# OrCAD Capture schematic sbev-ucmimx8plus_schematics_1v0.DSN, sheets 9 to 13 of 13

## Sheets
9 09. Audio Codec: size A3; title: SBEV-UCMIMX8PLUS      09. AUDIO CODEC
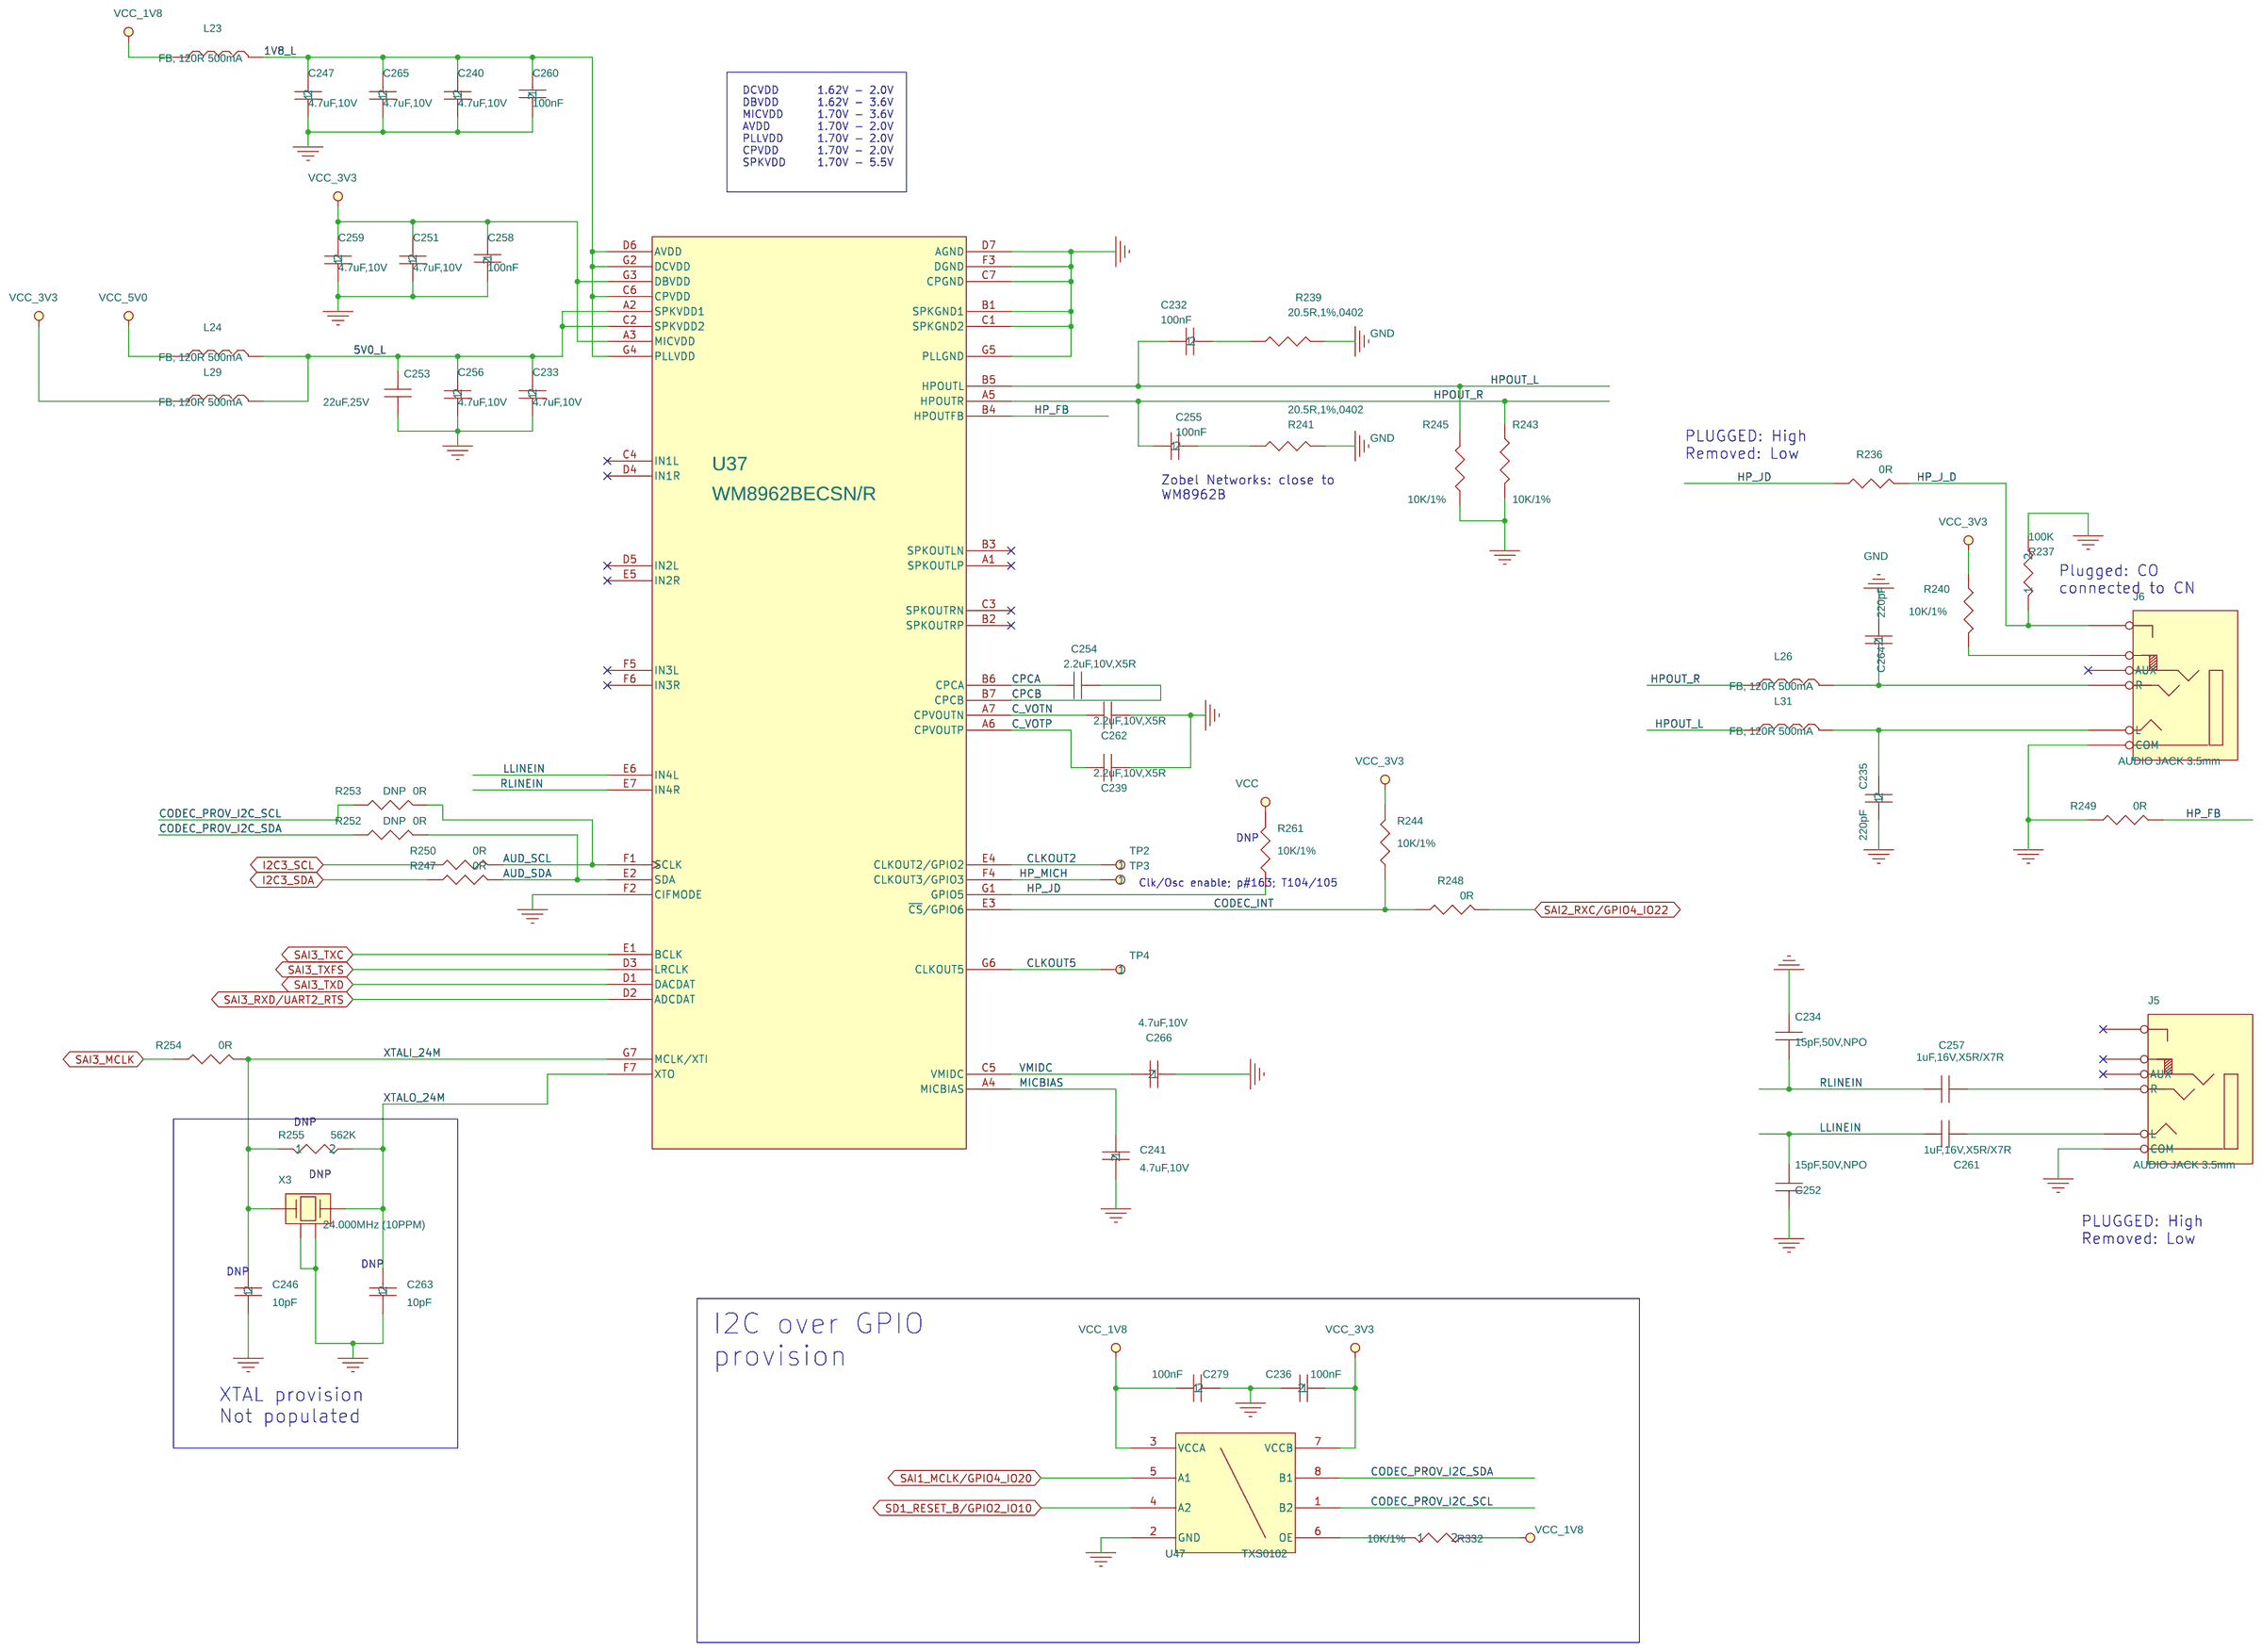
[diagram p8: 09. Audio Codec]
10 06. USB #2 and mini-PCIe: size A3; title: SBEV-UCMIMX8PLUS   06. USB #2 and mini-PCIe
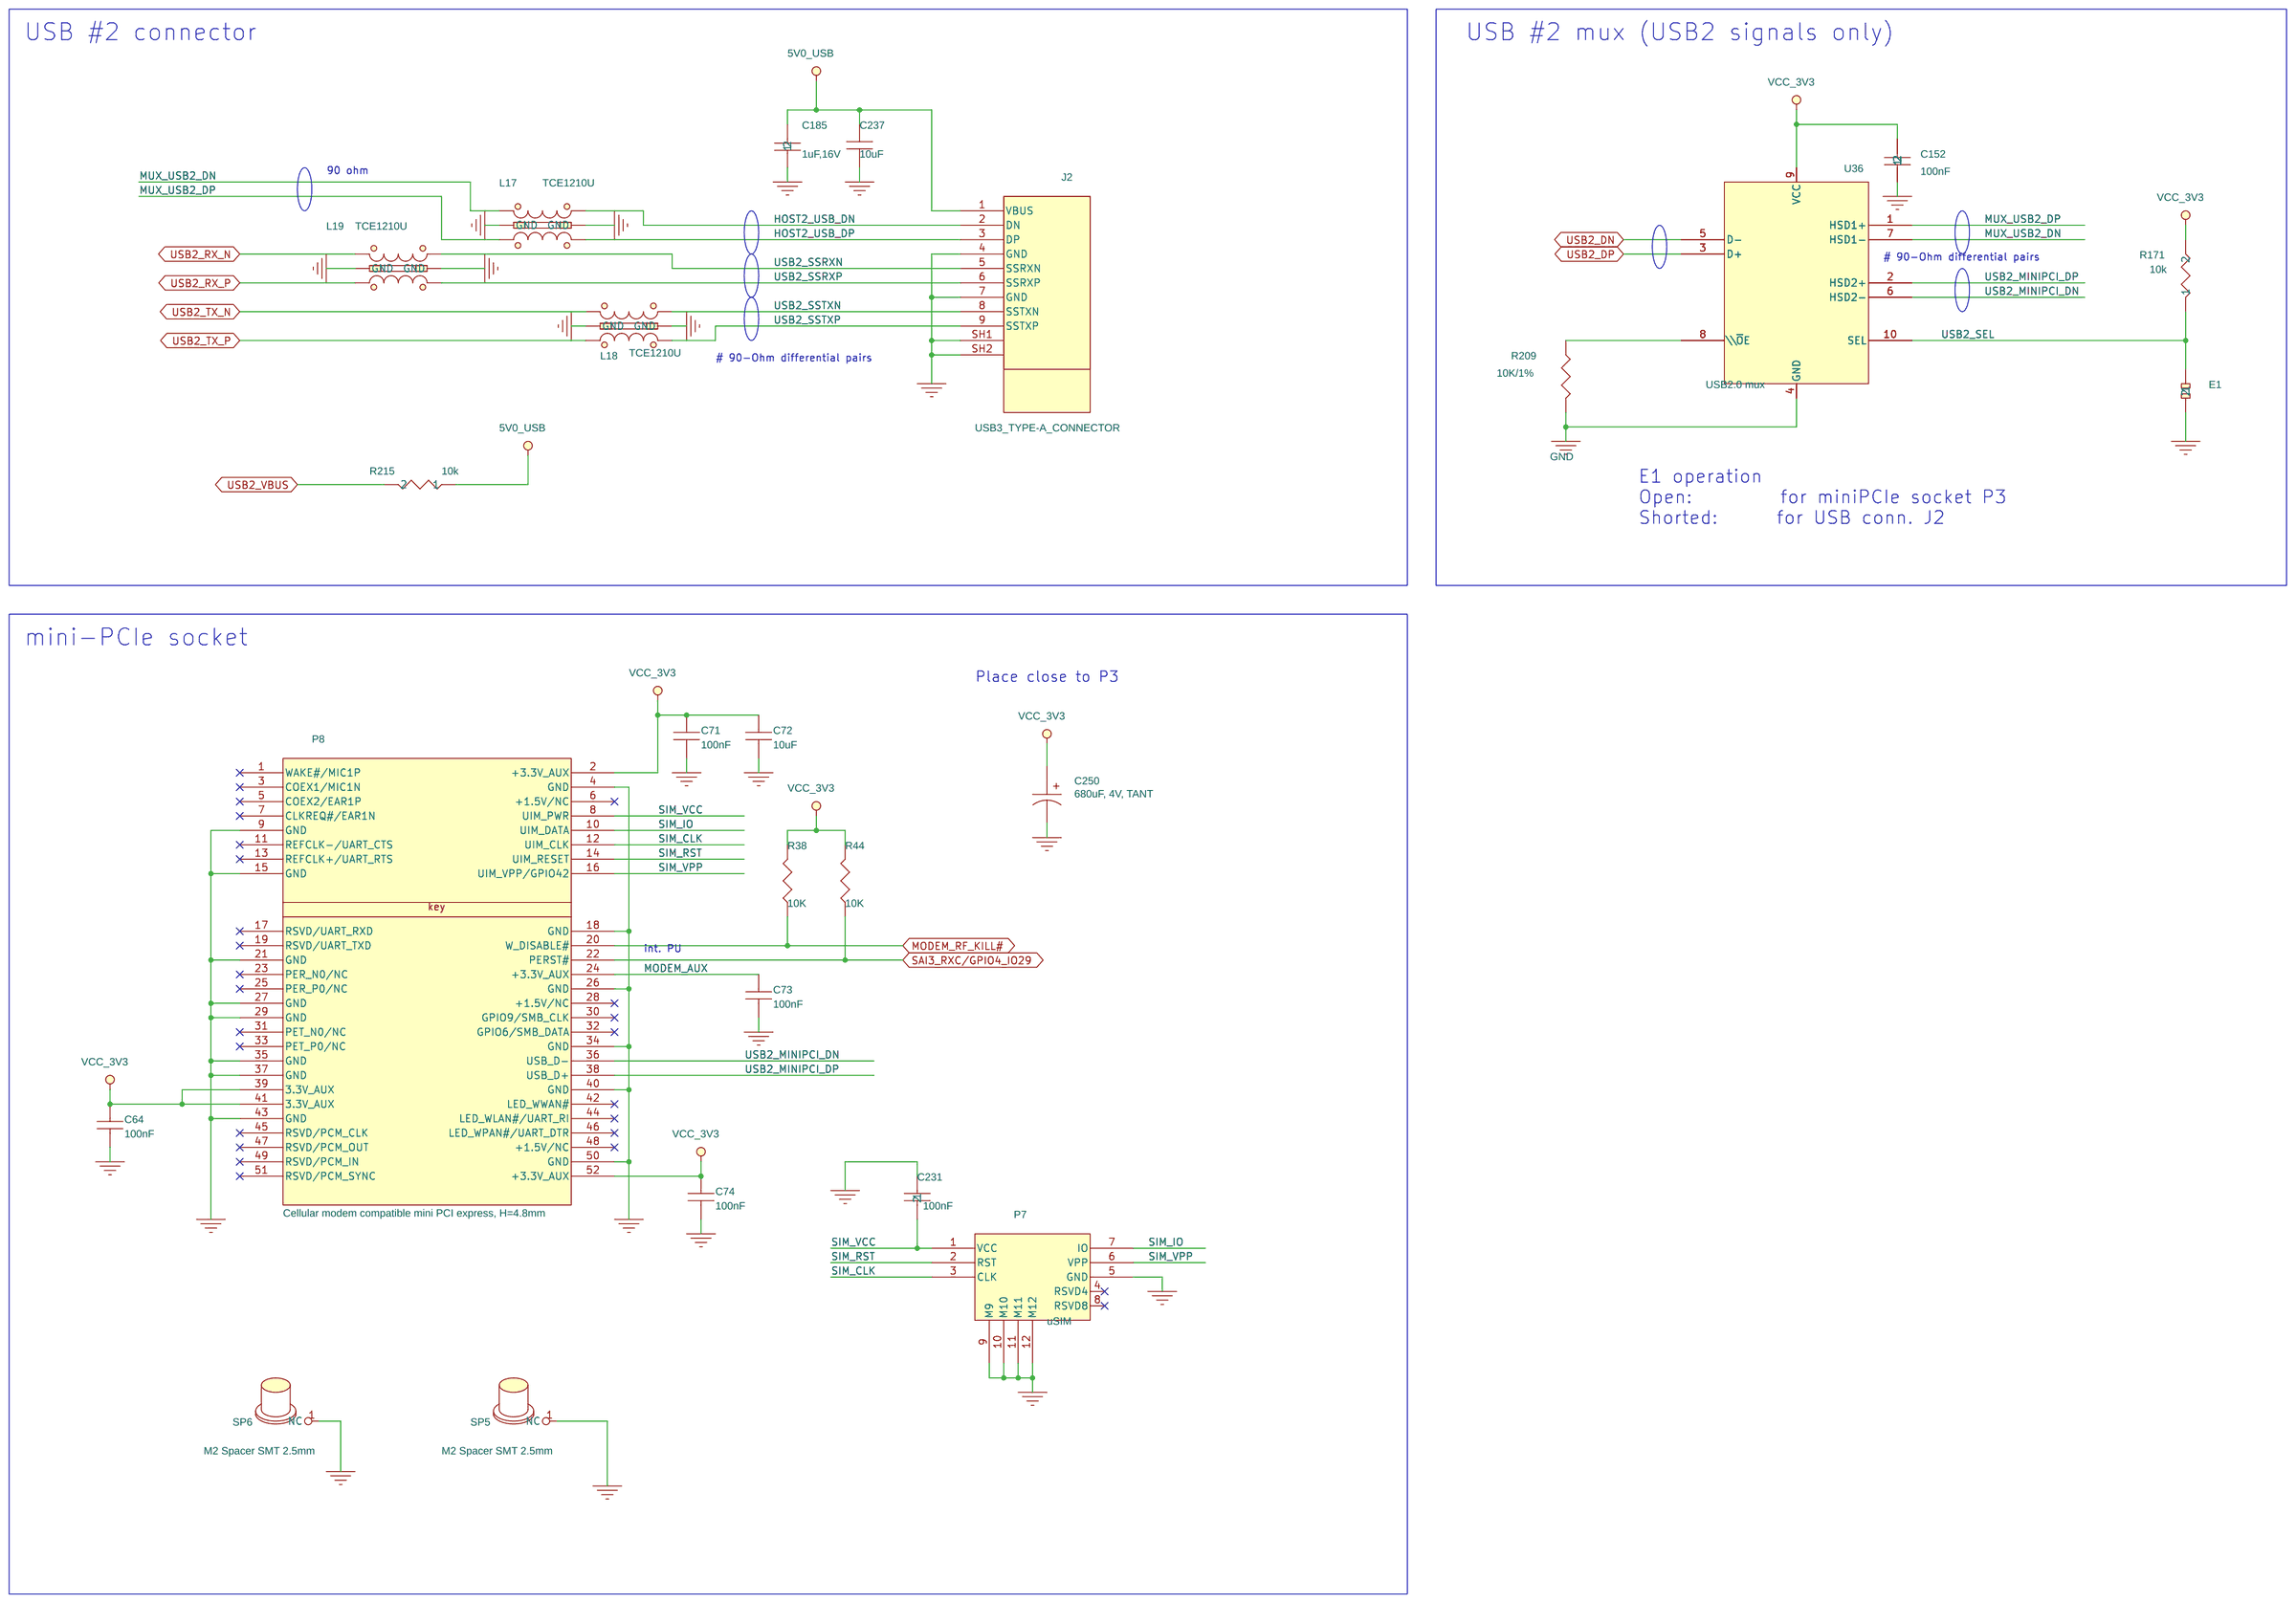
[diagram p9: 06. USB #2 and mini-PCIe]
11 13. DC input and spacers: size A3; title: SBEV-UCMIMX8PLUS    13. POWER
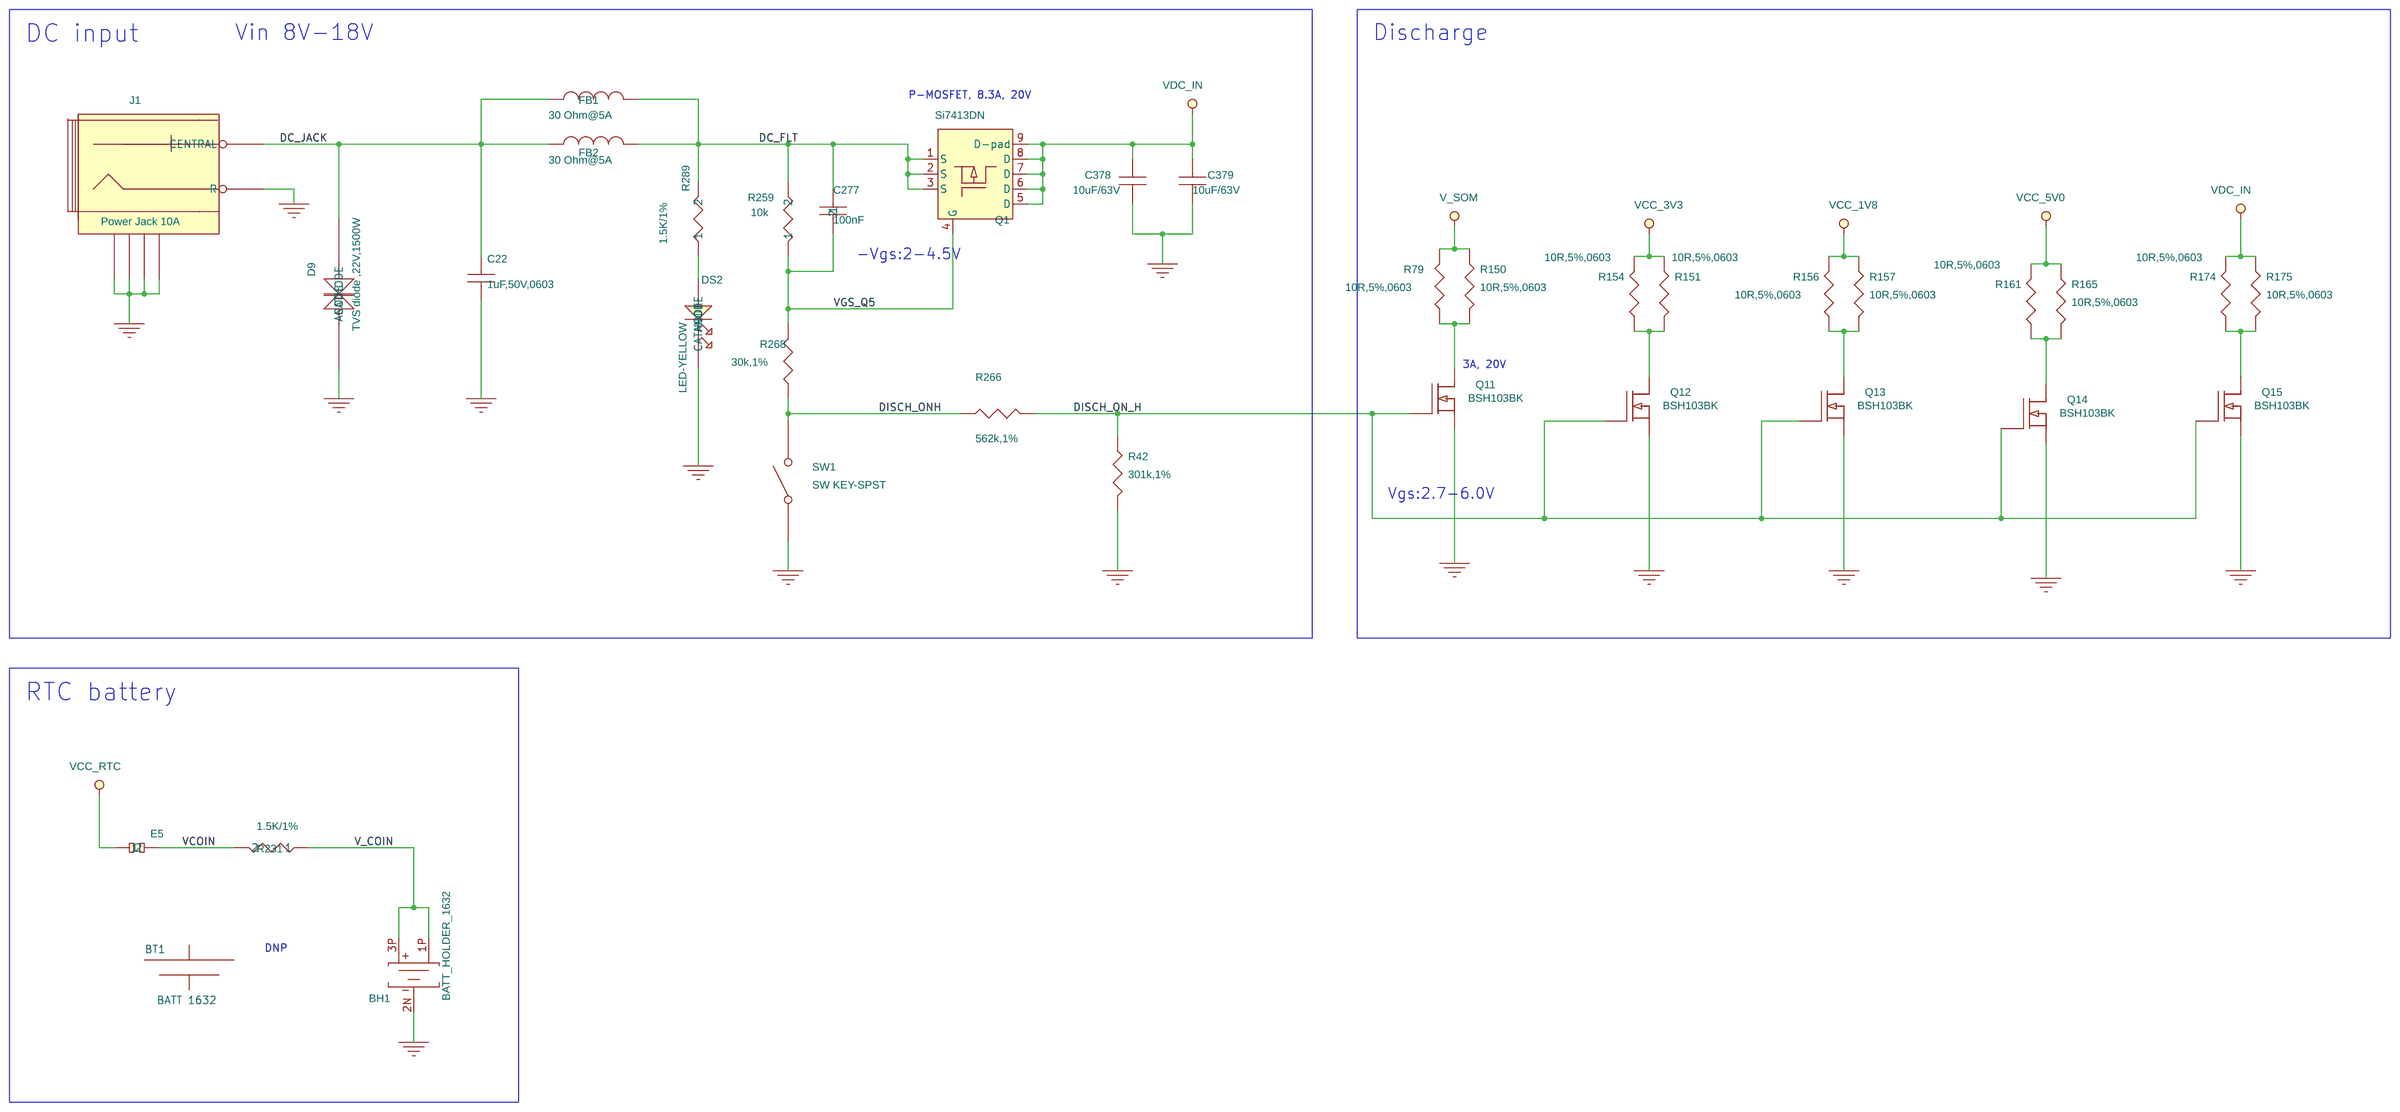
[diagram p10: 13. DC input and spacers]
12 12. Power: size A3; title: SBEV-UCMIMX8PLUS      12. Power
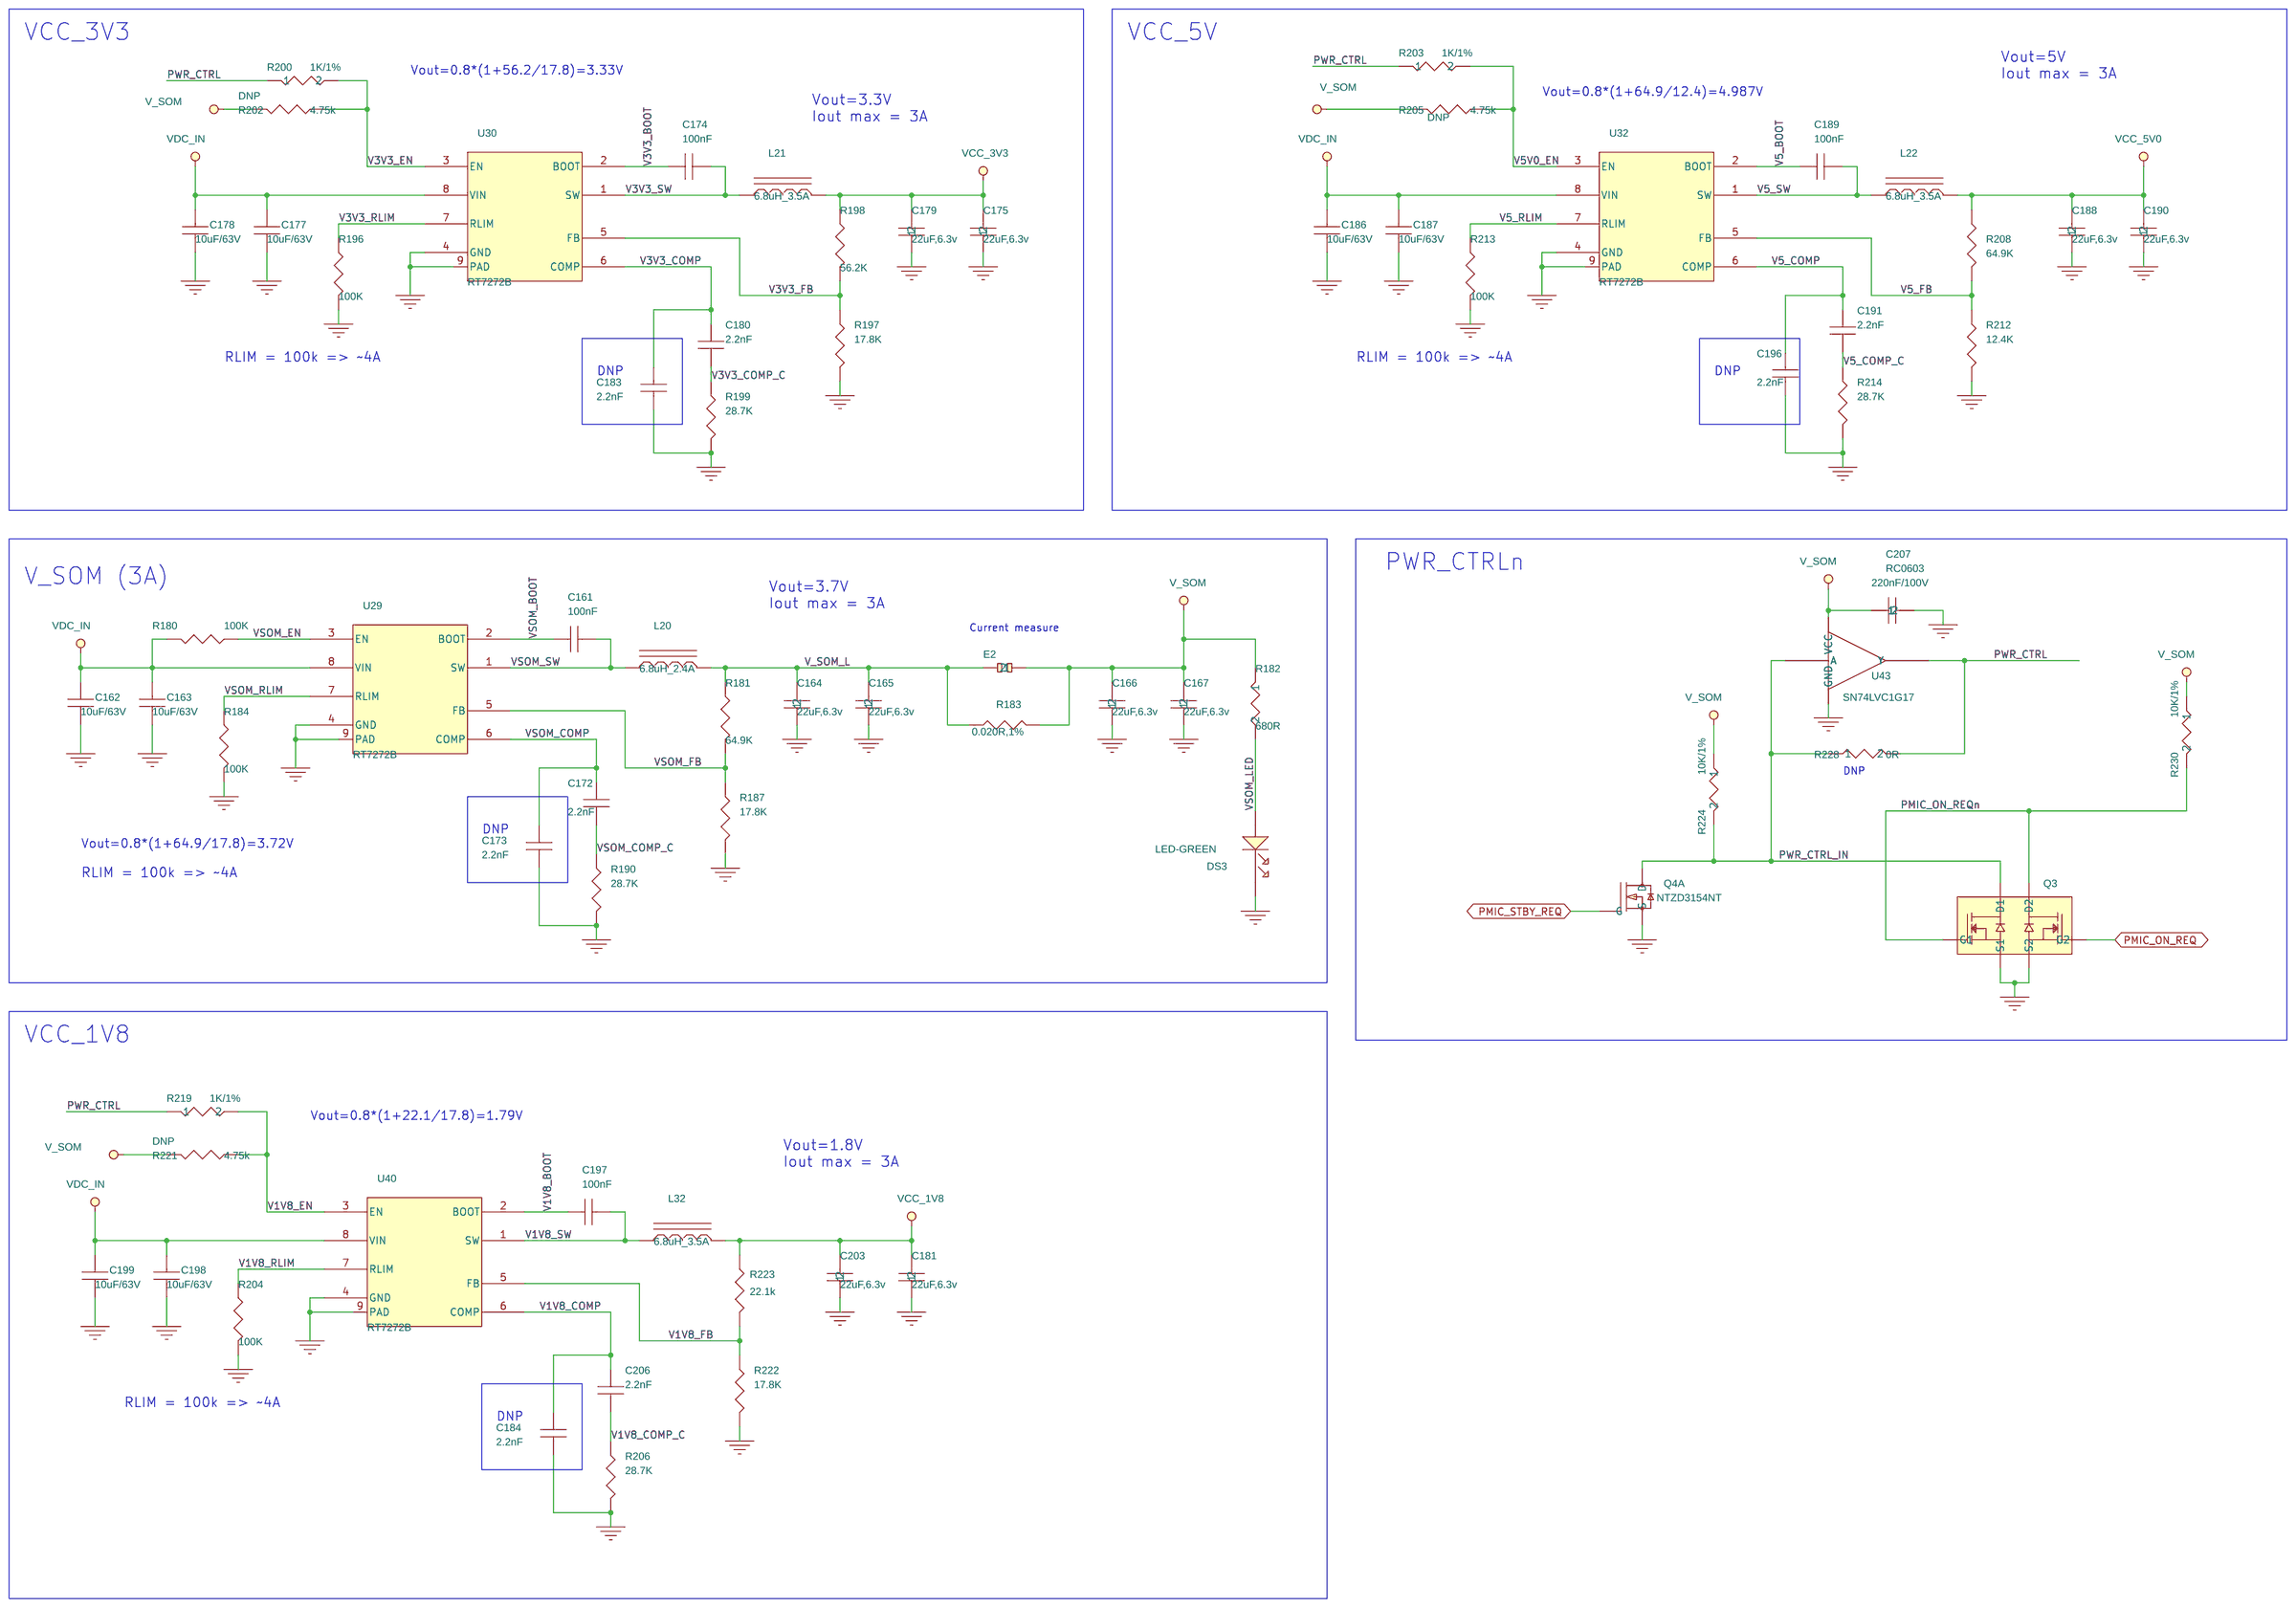
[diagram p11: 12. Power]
13 10. I/O headers, JTAG, GPIO exp: size A3; title: SBEV-UCMIMX8PLUS      10. UART, CAN, SPI, I2C, MISC
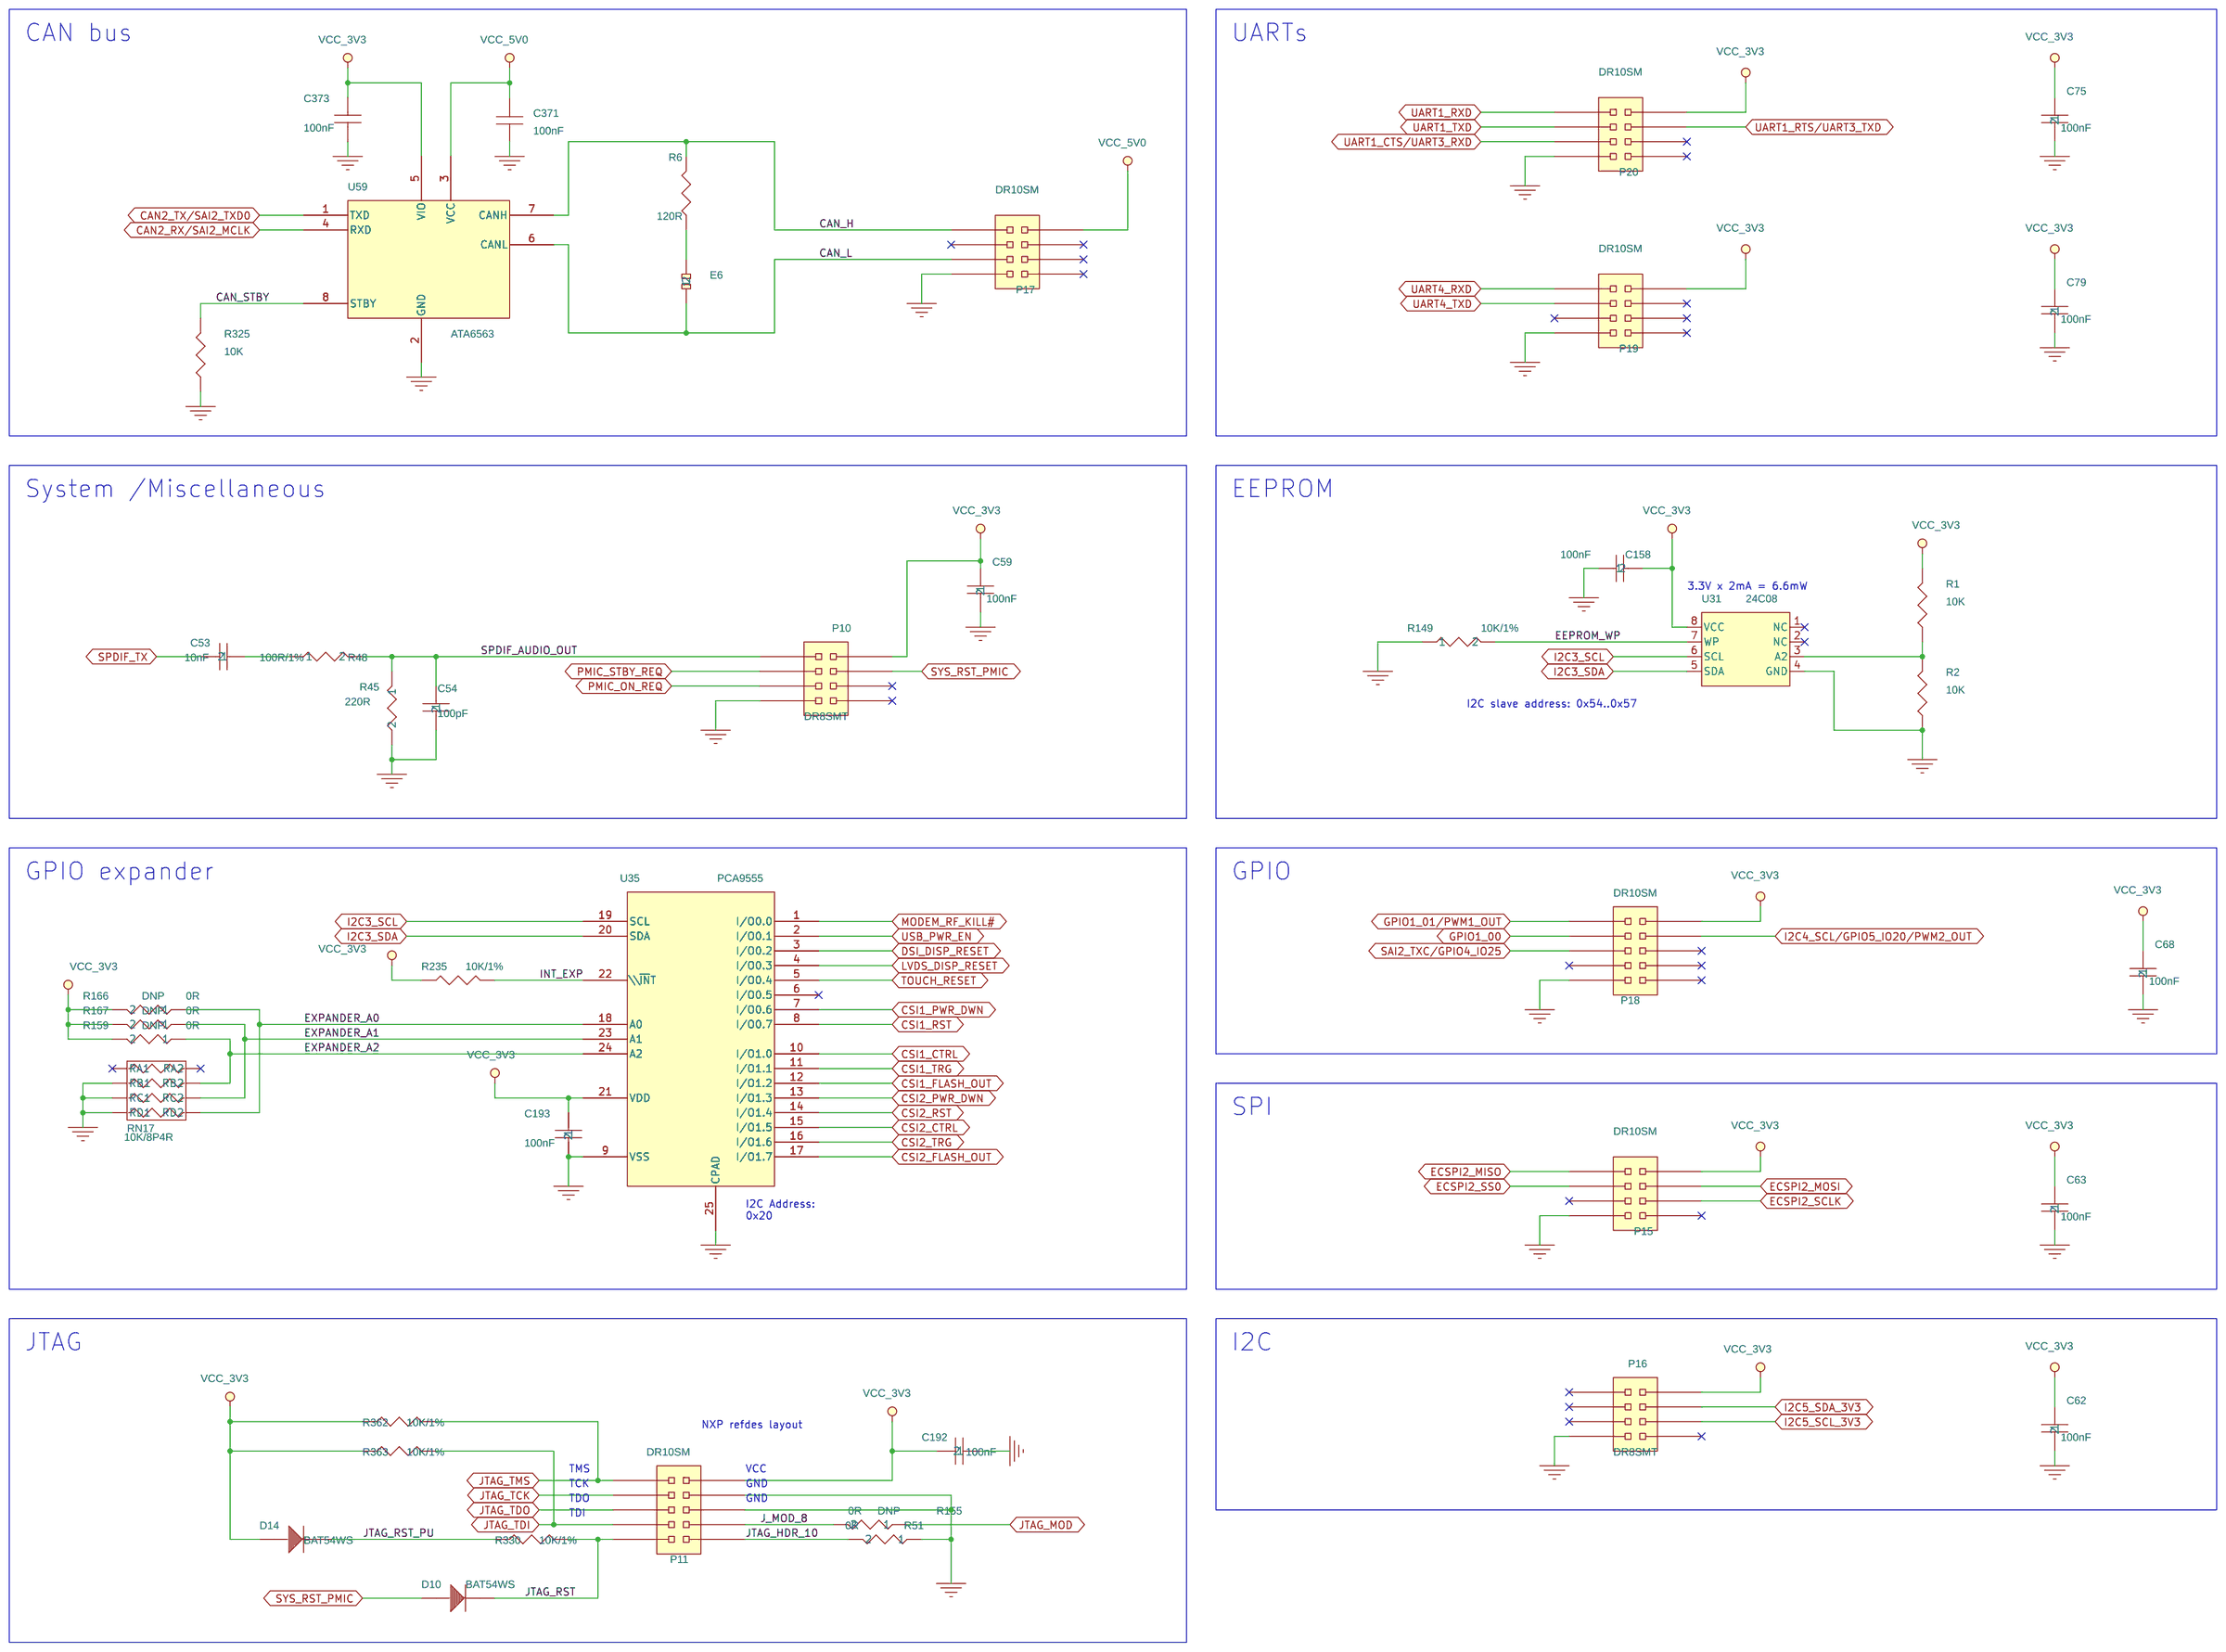
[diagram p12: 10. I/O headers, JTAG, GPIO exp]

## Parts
sheet 06. USB #2 and mini-PCIe
C64  100nF  [RC0402]
C71  100nF  [RC0402]
C72  10uF  [RC0603]
C73  100nF  [RC0402]
C74  100nF  [RC0402]
C152  100nF  [RC0402]
C185  1uF,16V  [RC0402]
C231  100nF  [RC0402]
C237  10uF  [C0603-08]
C250  680uF, 4V, TANT  [TANT7343]
E1  HDR1X2  [1X2THHDR]
J2  USB3_TYPE-A_CONNECTOR  [USB3_TYPEA]
L17  TCE1210U  [EMI1012-ESD]
L18  TCE1210U  [EMI1012-ESD]
L19  TCE1210U  [EMI1012-ESD]
P7  uSIM  [SKT-MicroSIM6-SM]
P8  Cellular modem compatible mini PCI express, H=4.8mm  [MINIPCIE-4]
R38  10K  [RC0402]
R44  10K  [RC0402]
R171  10k  [RC0402]
R209  10K/1%  [RC0402]
R215  10k  [RC0402]
SP5  M2 Spacer SMT 2.5mm  [SpacerM2H4SM]
SP6  M2 Spacer SMT 2.5mm  [SpacerM2H4SM]
U36  USB2.0 mux  [MO-255U1418E]
sheet 09. Audio Codec
C232  100nF  [RC0402]
C233  4.7uF,10V  [RC0402]
C234  15pF,50V,NPO  [RC0402]
C235  220pF  [RC0603]
C236  100nF  [RC0402]
C239  2.2uF,10V,X5R  [RC0402]
C240  4.7uF,10V  [RC0402]
C241  4.7uF,10V  [RC0402]
C246  10pF  [RC0402]
C247  4.7uF,10V  [RC0402]
C251  4.7uF,10V  [RC0402]
C252  15pF,50V,NPO  [RC0402]
C253  22uF,25V  [C0805]
C254  2.2uF,10V,X5R  [RC0402]
C255  100nF  [RC0402]
C256  4.7uF,10V  [RC0402]
C257  1uF,16V,X5R/X7R  [RC0402]
C258  100nF  [RC0402]
C259  4.7uF,10V  [RC0402]
C260  100nF  [RC0402]
C261  1uF,16V,X5R/X7R  [RC0402]
C262  2.2uF,10V,X5R  [RC0402]
C263  10pF  [RC0402]
C264  220pF  [RC0603]
C265  4.7uF,10V  [RC0402]
C266  4.7uF,10V  [RC0402]
C279  100nF  [RC0402]
J5  AUDIO JACK 3.5mm  [AJ35-4P-SW-SM]
J6  AUDIO JACK 3.5mm  [AJ35-4P-SW-SM]
L23  FB, 120R 500mA  [FB0402]
L24  FB, 120R 500mA  [FB0402]
L26  FB, 120R 500mA  [FB0402]
L29  FB, 120R 500mA  [FB0402]
L31  FB, 120R 500mA  [FB0402]
R236  0R  [RC0402]
R237  100K  [RC0402]
R239  20.5R,1%,0402  [RC0402]
R240  10K/1%  [RC0402]
R241  20.5R,1%,0402  [RC0402]
R243  10K/1%  [RC0402]
R244  10K/1%  [RC0402]
R245  10K/1%  [RC0402]
R247  0R  [RC0402]
R248  0R  [RC0402]
R249  0R  [RC0402]
R250  0R  [RC0402]
R252  0R  [RC0402]
R253  0R  [RC0402]
R254  0R  [RC0402]
R255  562K  [RC0402]
R261  10K/1%  [RC0402]
R332  10K/1%  [RC0402]
TP2  TESTPOINT SMT  [TESTPOINT]
TP3  TESTPOINT SMT  [TESTPOINT]
TP4  TESTPOINT SMT  [TESTPOINT]
U37  WM8962BECSN/R  [BGA49_0P5_3P62X4]
U47  TXS0102  [MO-187DA-8]
X3  24.000MHz (10PPM)  [OSC3225]
sheet 10. I/O headers, JTAG, GPIO exp
C53  10nF  [RC0402]
C54  100pF  [RC0402]
C59  100nF  [RC0402]
C62  100nF  [RC0402]
C63  100nF  [RC0402]
C68  100nF  [RC0402]
C75  100nF  [RC0402]
C79  100nF  [RC0402]
C158  100nF  [RC0402]
C192  100nF  [RC0402]
C193  100nF  [RC0402]
C371  100nF  [RC0402]
C373  100nF  [RC0402]
D10  BAT54WS  [SOD-323]
D14  BAT54WS  [SOD-323]
E6  HDR1X2  [1X2THHDR]
P10  DR8SMT  [2X4SMHDR]
P11  DR10SM  [2X5SMHDR]
P15  DR10SM  [2X4SMHDR]
P16  DR8SMT  [2X4SMHDR]
P17  DR10SM  [2X4SMHDR]
P18  DR10SM  [2X5SMHDR]
P19  DR10SM  [2X4SMHDR]
P20  DR10SM  [2X4SMHDR]
R1  10K  [RC0402]
R2  10K  [RC0402]
R6  120R  [RC0402]
R45  220R  [RC0402]
R48  100R/1%  [RC0402]
R51  0R  [RC0402]
R149  10K/1%  [RC0402]
R155  0R  [RC0402]
R159  0R  [RC0402]
R166  0R  [RC0402]
R167  0R  [RC0402]
R235  10K/1%  [RC0402]
R325  10K  [RC0402]
R330  10K/1%  [RC0402]
R362  10K/1%  [RC0402]
R363  10K/1%  [RC0402]
RN17  10K/8P4R  [RESNET8P0805]
U31  24C08  [MO-229VCED-2]
U35  PCA9555  [QFN4x4-24]
U59  ATA6563  [SOI8-150]
sheet 12. Power
C161  100nF  [RC0402]
C162  10uF/63V  [C1210H2_5]
C163  10uF/63V  [C1210H2_5]
C164  22uF,6.3v  [RC0603]
C165  22uF,6.3v  [RC0603]
C166  22uF,6.3v  [RC0603]
C167  22uF,6.3v  [RC0603]
C172  2.2nF  [RC0402]
C173  2.2nF  [RC0402]
C174  100nF  [RC0402]
C175  22uF,6.3v  [RC0603]
C177  10uF/63V  [C1210H2_5]
C178  10uF/63V  [C1210H2_5]
C179  22uF,6.3v  [RC0603]
C180  2.2nF  [RC0402]
C181  22uF,6.3v  [RC0603]
C183  2.2nF  [RC0402]
C184  2.2nF  [RC0402]
C186  10uF/63V  [C1210H2_5]
C187  10uF/63V  [C1210H2_5]
C188  22uF,6.3v  [RC0603]
C189  100nF  [RC0402]
C190  22uF,6.3v  [RC0603]
C191  2.2nF  [RC0402]
C196  2.2nF  [RC0402]
C197  100nF  [RC0402]
C198  10uF/63V  [C1210H2_5]
C199  10uF/63V  [C1210H2_5]
C203  22uF,6.3v  [RC0603]
C206  2.2nF  [RC0402]
C207  220nF/100V  [RC0603]
DS3  LED-GREEN  [LED-1206]
E2  HDR1X2  [1X2THHDR]
L20  6.8uH_2.4A  [IND6x5_5x3]
L21  6.8uH_3.5A  [IND6x5_5x3]
L22  6.8uH_3.5A  [IND6x5_5x3]
L32  6.8uH_3.5A  [IND6x5_5x3]
Q3  0.5A,20V,Vgs max 6V  [SOT-563-6]
Q4  NTZD3154NT  [SOT-563-6]  (section A)
R180  100K  [RC0402]
R181  64.9K  [RC0402]
R182  680R  [RC0402]
R183  0.020R,1%  [R1206]
R184  100K  [RC0402]
R187  17.8K  [RC0402]
R190  28.7K  [RC0402]
R196  100K  [RC0402]
R197  17.8K  [RC0402]
R198  56.2K  [RC0402]
R199  28.7K  [RC0402]
R200  1K/1%  [RC0402]
R202  4.75k  [RC0402]
R203  1K/1%  [RC0402]
R204  100K  [RC0402]
R205  4.75k  [RC0402]
R206  28.7K  [RC0402]
R208  64.9K  [RC0402]
R212  12.4K  [RC0402]
R213  100K  [RC0402]
R214  28.7K  [RC0402]
R219  1K/1%  [RC0402]
R221  4.75k  [RC0402]
R222  17.8K  [RC0402]
R223  22.1k  [RC0402]
R224  10K/1%  [RC0402]
R228  0R  [RC0402]
R230  10K/1%  [RC0402]
U29  RT7272B  [PSOP-8-2X2]
U30  RT7272B  [PSOP-8-2X2]
U32  RT7272B  [PSOP-8-2X2]
U40  RT7272B  [PSOP-8-2X2]
U43  SN74LVC1G17
sheet 13. DC input and spacers
BH1  BATT_HOLDER_1632  [BattH16mm-SM]
BT1  BATT 1632
C22  1uF,50V,0603  [RC0603]
C277  100nF  [RC0402]
C378  10uF/63V  [C1210H2_5]
C379  10uF/63V  [C1210H2_5]
D9  TVS diode ,22V,1500W  [DO-214AB]
DS2  LED-YELLOW  [LED-1206]
E5  HDR1X2  [1X2THHDR]
FB1  30 Ohm@5A  [FB0603]
FB2  30 Ohm@5A  [FB0603]
J1  Power Jack 10A  [PJ-0810-TH]
Q1  Si7413DN  [Powerpak1212-8]
Q11  BSH103BK  [SOT23]
Q12  BSH103BK  [SOT23]
Q13  BSH103BK  [SOT23]
Q14  BSH103BK  [SOT23]
Q15  BSH103BK  [SOT23]
R42  301k,1%  [RC0402]
R79  10R,5%,0603  [RC0603]
R150  10R,5%,0603  [RC0603]
R151  10R,5%,0603  [RC0603]
R154  10R,5%,0603  [RC0603]
R156  10R,5%,0603  [RC0603]
R157  10R,5%,0603  [RC0603]
R161  10R,5%,0603  [RC0603]
R165  10R,5%,0603  [RC0603]
R174  10R,5%,0603  [RC0603]
R175  10R,5%,0603  [RC0603]
R231  1.5K/1%  [RC0402]
R259  10k  [RC0402]
R266  562k,1%  [RC0402]
R268  30k,1%  [RC0402]
R289  1.5K/1%  [RC0402]
SW1  SW KEY-SPST

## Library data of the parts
C64 C71 C73 C74 C161 C174 C189 C197 = 100nF,_10V,_X7R,_10%,_0402_0: CLABCONF0: =SBEV-UCMIMX8PLUS; Group: LAN2
C72 = 10uF,6.3V,0603,20%X5R: CLABCONF0: =SBEV-UCMIMX8PLUS; P/N: 151B10610S
C152 = 100nF,_10V,_X7R,_10%,_0402_2: CLABCONF0: =SBEV-UCMIMX8PLUS; Group: LAN2
C185 = 100nF,_10V,_X7R,_10%,_0402: CLABCONF0: =SBEV-UCMIMX8PLUS; P/N: 151C10500S
C68 C231 C236 = 100nF,_10V,_X7R,_10%,_0402_1: CLABCONF0: =SBEV-UCMIMX8PLUS
C237 = 10uF,6_0.3V,0603,20%X5R: CLABCONF0: =SBEV-UCMIMX8PLUS
C250 = CAPACITOR_POL: CLABCONF0: =SBEV-UCMIMX8PLUS; P/N: 154A687D0S
E1 E2 E5 E6 = HDR_1x2_100MIL_TH_JUMPER: CLABCONF0: =SBEV-UCMIMX8PLUS
J2 = USB3_TYPEA_CONNECTER_0: CLABCONF0: =SBEV-UCMIMX8PLUS
L17-L19 = ESD_CHOKE_DIFFx2_10: CLABCONF0: =SBEV-UCMIMX8PLUS; P/N: 142D11801S
P7 = uSIM_SOCKET_0: CLABCONF0: =SBEV-UCMIMX8PLUS
P8 = Conn.,_Mini-PCIe,_for_SIM5360: CLABCONF0: =SBEV-UCMIMX8PLUS; P/N: 182K05203S
R38 = 10K,1%,0402,1_16W_0_1: CLABCONF0: =SBEV-UCMIMX8PLUS; Group: Always
R44 = 10K,1%,0402,1_16W_0: CLABCONF0: =SBEV-UCMIMX8PLUS; Group: Always
R171 = 1M_,5%,_0402_1: CLABCONF0: =SBEV-UCMIMX8PLUS; P/N: 161C10021S
R209 = 10K,1%,0402,1_16W_0_2: CLABCONF0: =SBEV-UCMIMX8PLUS
R215 R259 = 1M_,5%,_0402: CLABCONF0: =SBEV-UCMIMX8PLUS; P/N: 161C10021S
SP5 = Spacer_SMT,_M2,_4mm_1: CLABCONF0: =SBEV-UCMIMX8PLUS; P/N: 383B52531S
SP6 = Spacer_SMT,_M2,_4mm_0: CLABCONF0: =SBEV-UCMIMX8PLUS; P/N: 383B52531S
U36 = USB2_0.0_mux: CLABCONF0: =SBEV-UCMIMX8PLUS; P/N: 116A72220S
C62 C232 C277 = 100nF,_10V,_X7R,_10%,_0402: CLABCONF0: =SBEV-UCMIMX8PLUS
C233 = 15pF,_50V,_NPO,_5%,_0402_2: CLABCONF0: =SBEV-UCMIMX8PLUS; P/N: 151B47500S
C234 C252 = CAP_NP: CLABCONF0: =SBEV-UCMIMX8PLUS; P/N: 151D15000S
C235 = 220pF,50V,NPO,0603: CLABCONF0: =SBEV-UCMIMX8PLUS
C239 C254 C262 = CAP_NP: CLABCONF0: =SBEV-UCMIMX8PLUS; P/N: 151B22500S
C240 = 15pF,_50V,_NPO,_5%,_0402_6: CLABCONF0: =SBEV-UCMIMX8PLUS; P/N: 151B47500S
C241 = 15pF,_50V,_NPO,_5%,_0402_1: CLABCONF0: =SBEV-UCMIMX8PLUS; P/N: 151B47500S
C246 = 10pF,50V,NPO,_5%,_0402_1: CLABCONF0: DNP
C247 = 15pF,_50V,_NPO,_5%,_0402: CLABCONF0: =SBEV-UCMIMX8PLUS; P/N: 151B47500S
C251 = 15pF,_50V,_NPO,_5%,_0402_5: CLABCONF0: =SBEV-UCMIMX8PLUS; P/N: 151B47500S
C253 = CAP_NP: CLABCONF0: =SBEV-UCMIMX8PLUS; P/N: 151C22620S
C63 C255 = 100nF,_10V,_X7R,_10%,_0402_5: CLABCONF0: =SBEV-UCMIMX8PLUS
C256 = 15pF,_50V,_NPO,_5%,_0402_8: CLABCONF0: =SBEV-UCMIMX8PLUS; P/N: 151B47500S
C257 C261 = CAP_NP: CLABCONF0: =SBEV-UCMIMX8PLUS; P/N: 151C10500S
C75 C258 = 100nF,_10V,_X7R,_10%,_0402_3: CLABCONF0: =SBEV-UCMIMX8PLUS
C259 = 15pF,_50V,_NPO,_5%,_0402_3: CLABCONF0: =SBEV-UCMIMX8PLUS; P/N: 151B47500S
C79 C260 = 100nF,_10V,_X7R,_10%,_0402_4: CLABCONF0: =SBEV-UCMIMX8PLUS
C263 = 10pF,50V,NPO,_5%,_0402: CLABCONF0: DNP
C264 = 220pF,50V,NPO,0603_1: CLABCONF0: =SBEV-UCMIMX8PLUS
C265 = 15pF,_50V,_NPO,_5%,_0402_4: CLABCONF0: =SBEV-UCMIMX8PLUS; P/N: 151B47500S
C266 = 15pF,_50V,_NPO,_5%,_0402_7: CLABCONF0: =SBEV-UCMIMX8PLUS; P/N: 151B47500S
C158 C279 = 100nF,_10V,_X7R,_10%,_0402_2: CLABCONF0: =SBEV-UCMIMX8PLUS
J5 J6 = Audio_JACK,_STEREO+AUX+SW_3.5mm: CLABCONF0: =SBEV-UCMIMX8PLUS
L23 L24 L26 L31 = Ferrit_330R-100Mhz,1.2A: CLABCONF0: =SBEV-UCMIMX8PLUS; P/N: 147D12102S
L29 = Ferrit_330R-100Mhz,1.2A: CLABCONF0: DNP; P/N: 147D12102S
R236 = 0R,_0402_0_6: CLABCONF0: =SBEV-UCMIMX8PLUS
R237 = 100K,_0402: CLABCONF0: =SBEV-UCMIMX8PLUS; P/N: 161C10031S
R239 R241 = RESISTOR: CLABCONF0: =SBEV-UCMIMX8PLUS; P/N: 161C20R51S
R240 = 10K,1%,0402,1_16W_0_3: CLABCONF0: =SBEV-UCMIMX8PLUS
R2 R243 = 10K,1%,0402,1_16W_0_1: CLABCONF0: =SBEV-UCMIMX8PLUS
R244 = 10K,1%,0402,1_16W_0_4: CLABCONF0: =SBEV-UCMIMX8PLUS
R1 R245 = 10K,1%,0402,1_16W_0: CLABCONF0: =SBEV-UCMIMX8PLUS
R247 = 0R,_0402_0_1: CLABCONF0: =SBEV-UCMIMX8PLUS
R248 = 0R,_0402_0_3: CLABCONF0: =SBEV-UCMIMX8PLUS
R249 = 0R,_0402_0_7: CLABCONF0: =SBEV-UCMIMX8PLUS
R250 = 0R,_0402_0_2: CLABCONF0: =SBEV-UCMIMX8PLUS
R252 = 0R,_0402_0_4: CLABCONF0: DNP
R253 = 0R,_0402_0: CLABCONF0: DNP
R254 = 0R,_0402_0_5: CLABCONF0: =SBEV-UCMIMX8PLUS
R255 = 10M,5%,0402,1_16W: CLABCONF0: DNP; P/N: 161C56231S
R261 R363 = 10K,1%,0402,1_16W_0_2: CLABCONF0: DNP
R149 R224 R332 = 10K,1%,0402,1_16W: CLABCONF0: =SBEV-UCMIMX8PLUS
TP2-TP4 = TESTPOINT: CLABCONF0: DNP; P/N: 188Z01370S
U37 = WM8962_BGA_49P_A: IC AUDIO CODEC 24BIT DAC 2 CH ADC 1.8V BGA49; 3D_Mechanical_Footprint_File: ftp://fcl.am.freescale.net/ALLEGRO/step/BGA49_0P5_3P62X4.STEP; AGILE_PN: 315-80353; CAD_APPROVED: Yes; CLABCONF0: =SBEV-UCMIMX8PLUS; HEIGHT: 0.75MM; MFG_NAME01: WOLFSON MICROELECTRONICS; P/N: 117A10070S; ROHS: Yes; VOLTAGE: 1.8V
U47 = TXS0102_0: CLABCONF0: =SBEV-UCMIMX8PLUS; P/N: 116A01020S
X3 = XTAL,24.000Mhz,100ppm,Ind,3x5mm: CLABCONF0: DNP; P/N: 141B24605I
C53 = 10nF,_25V,_X7R,_10%,_0402: CLABCONF0: =SBEV-UCMIMX8PLUS
C54 = 100pF,_50V,_NPO,_5%,_0402: CLABCONF0: =SBEV-UCMIMX8PLUS
C59 = 100nF,_10V,_X7R,_10%,_0402_7: CLABCONF0: =SBEV-UCMIMX8PLUS
C192 = 100nF,_10V,_X7R,_10%,_0402_6: CLABCONF0: =SBEV-UCMIMX8PLUS
C193 = 100nF,_10V,_X7R,_10%,_0402_8: CLABCONF0: =SBEV-UCMIMX8PLUS
C371 C373 = 100nF,_10V,_X7R,_10%,_0402_0: CLABCONF0: =SBEV-UCMIMX8PLUS
D10 D14 = BAT54WS_0: CLABCONF0: =SBEV-UCMIMX8PLUS
P10 P16 = HDR_2x7_100MIL_RA_TH_SHRD_0: CLABCONF0: =SBEV-UCMIMX8PLUS; P/N: 190C00801S
P11 P18 = HDR_2x5_100MIL_SMT: CLABCONF0: =SBEV-UCMIMX8PLUS
P15 P17 P19 P20 = HDR_2x5_100MIL_SMT_2: CLABCONF0: =SBEV-UCMIMX8PLUS; P/N: 190C00801S
R6 = 0R,_0402_0: CLABCONF0: =SBEV-UCMIMX8PLUS; Group: Always; P/N: 161C12001S
R45 = 220R,5%,0402,1_16W: CLABCONF0: =SBEV-UCMIMX8PLUS
R48 = 100R,1%,0402,1_16W: CLABCONF0: =SBEV-UCMIMX8PLUS
R51 = 0R,_0402_1: CLABCONF0: =SBEV-UCMIMX8PLUS
R155 = 0R,_0402_1_4: CLABCONF0: DNP
R159 = 0R,_0402_1_1: CLABCONF0: DNP
R166 = 0R,_0402_1_3: CLABCONF0: DNP
R167 = 0R,_0402_1_2: CLABCONF0: DNP
R235 = 10K,1%,0402,1_16W_0_6: CLABCONF0: =SBEV-UCMIMX8PLUS
R325 = 10K,1%,0402,1_16W_0_5: CLABCONF0: =SBEV-UCMIMX8PLUS
R330 = 10K,1%,0402,1_16W_0_4: CLABCONF0: DNP
R362 = 10K,1%,0402,1_16W_0_3: CLABCONF0: DNP
RN17 = RN,10K,8P4R@0805: CLABCONF0: =SBEV-UCMIMX8PLUS
U31 = 24C02,_serial_EE,_2KB,_I2C_0: CLABCONF0: =SBEV-UCMIMX8PLUS; P/N: 111S31000S
U35 = PCA9555_1: CLABCONF0: =SBEV-UCMIMX8PLUS
U59 = ATA6563: CLABCONF0: =SBEV-UCMIMX8PLUS; P/N: 116A00380S
C162 C163 = 22uF_25V: CLABCONF0: =SBEV-UCMIMX8PLUS; P/N: 151D10630S
C164 = 100nF,_10V,_X7R,_10%,_0402_5: CLABCONF0: =SBEV-UCMIMX8PLUS; P/N: 151B22610S
C165 = 100nF,_10V,_X7R,_10%,_0402_8: CLABCONF0: =SBEV-UCMIMX8PLUS; P/N: 151B22610S
C166 = 100nF,_10V,_X7R,_10%,_0402_9: CLABCONF0: =SBEV-UCMIMX8PLUS; P/N: 151B22610S
C167 = 100nF,_10V,_X7R,_10%,_0402_2: CLABCONF0: =SBEV-UCMIMX8PLUS; P/N: 151B22610S
C172 = 2.2nF,_50V,_X7R,_10%,_0402: CLABCONF0: =SBEV-UCMIMX8PLUS
C173 = 2.2nF,_50V,_X7R,_10%,_0402_6: CLABCONF0: DNP
C175 = 100nF,_10V,_X7R,_10%,_0402_1: CLABCONF0: =SBEV-UCMIMX8PLUS; P/N: 151B22610S
C177 C178 C186 C187 C198 C199 C378 C379 = 22uF_25V: CLABCONF0: =SBEV-UCMIMX8PLUS; P/N: 151E10680S
C179 = 100nF,_10V,_X7R,_10%,_0402_7: CLABCONF0: =SBEV-UCMIMX8PLUS; P/N: 151B22610S
C180 = 2.2nF,_50V,_X7R,_10%,_0402_1: CLABCONF0: =SBEV-UCMIMX8PLUS
C181 = 100nF,_10V,_X7R,_10%,_0402_3: CLABCONF0: =SBEV-UCMIMX8PLUS; P/N: 151B22610S
C183 = 2.2nF,_50V,_X7R,_10%,_0402_3: CLABCONF0: DNP
C184 = 2.2nF,_50V,_X7R,_10%,_0402_4: CLABCONF0: DNP
C188 = 100nF,_10V,_X7R,_10%,_0402: CLABCONF0: =SBEV-UCMIMX8PLUS; P/N: 151B22610S
C190 = 100nF,_10V,_X7R,_10%,_0402_6: CLABCONF0: =SBEV-UCMIMX8PLUS; P/N: 151B22610S
C191 = 2.2nF,_50V,_X7R,_10%,_0402_7: CLABCONF0: =SBEV-UCMIMX8PLUS
C196 = 2.2nF,_50V,_X7R,_10%,_0402_2: CLABCONF0: DNP
C203 = 100nF,_10V,_X7R,_10%,_0402_4: CLABCONF0: =SBEV-UCMIMX8PLUS; P/N: 151B22610S
C206 = 2.2nF,_50V,_X7R,_10%,_0402_5: CLABCONF0: =SBEV-UCMIMX8PLUS
C207 = 100nF,_10V,_X7R,_10%,_0402_10: CLABCONF0: =SBEV-UCMIMX8PLUS; P/N: 151E22410S
DS3 = LED-GREEN_1206_2: CLABCONF0: =SBEV-UCMIMX8PLUS
L20 = IND_6.8uH_3.5A: CLABCONF0: =SBEV-UCMIMX8PLUS; P/N: 147A6R804S
L21 L22 L32 = IND_6.8uH_3.5A: CLABCONF0: =SBEV-UCMIMX8PLUS; P/N: 147A6R802S
Q3 = DUAL_N-MOSFET,_0.5A_20V: CLABCONF0: =SBEV-UCMIMX8PLUS
Q4 = N-MOSFET_Dual: CLABCONF0: =SBEV-UCMIMX8PLUS; P/N: 131D31540S
R180 R184 R196 R204 R213 = 100K,_0402_0: CLABCONF0: =SBEV-UCMIMX8PLUS
R181 R208 = 10.5K_1%,0402: CLABCONF0: =SBEV-UCMIMX8PLUS; P/N: 161C64921S
R182 = 47K,_0402: CLABCONF0: =SBEV-UCMIMX8PLUS; P/N: 161C68001S
R183 = RESISTOR: CLABCONF0: =SBEV-UCMIMX8PLUS; P/N: 161G02011S; Part Name: Res., 0.020R, 1%, 1206, 1/2W (Current sense)
R187 R197 R222 = 2.37K_1%,_0402: CLABCONF0: =SBEV-UCMIMX8PLUS; P/N: 161C17821S
R190 R199 R206 R214 = 40.2k_1%: CLABCONF0: =SBEV-UCMIMX8PLUS; P/N: 161C28721S
R198 = 10.5K_1%,0402: CLABCONF0: =SBEV-UCMIMX8PLUS; P/N: 161C56221S
R200 = 1K,1%,0402,1_16W_2: CLABCONF0: =SBEV-UCMIMX8PLUS; Group: CAN
R202 R205 R221 = 100K,_0402_0: CLABCONF0: DNP; P/N: 161C47511S
R203 = 1K,1%,0402,1_16W_1: CLABCONF0: =SBEV-UCMIMX8PLUS; Group: CAN
R212 = 2.37K_1%,_0402: CLABCONF0: =SBEV-UCMIMX8PLUS; P/N: 161C12421S
R219 = 1K,1%,0402,1_16W: CLABCONF0: =SBEV-UCMIMX8PLUS; Group: CAN
R223 = RESISTOR: CLABCONF0: =SBEV-UCMIMX8PLUS; P/N: 161C22121S
R228 = 0R,_0402: CLABCONF0: DNP
R230 = 10K,1%,0402,1_16W_1: CLABCONF0: =SBEV-UCMIMX8PLUS
U29 U30 U32 U40 = RT7272B,Converter,3A,36V: CLABCONF0: =SBEV-UCMIMX8PLUS; P/N: 123V30000S
U43 = SN74LVC1G17: CLABCONF0: =SBEV-UCMIMX8PLUS; P/N: 106D90000S
BH1 = BATT_HOLDER_1: CLABCONF0: =SBEV-UCMIMX8PLUS; P/N: 190Z00300S
BT1 = BATT_2032: CLABCONF0: =SBEV-UCMIMX8PLUS; P/N: 210C30006
C22 = CAP_NP: CLABCONF0: =SBEV-UCMIMX8PLUS; P/N: 151D10510S; Part Name: Cap., 1uF, 50V, X5R/X7R, 10%, 0603
D9 = Diode_,TVS_,15V,1500W_0: CLABCONF0: =SBEV-UCMIMX8PLUS; P/N: 132D10030S
DS2 = LED-RED_1206: CLABCONF0: =SBEV-UCMIMX8PLUS; P/N: 139A10110S
FB1 = Ferrite_bead_,_30_Ohm@5A_1: CLABCONF0: =SBEV-UCMIMX8PLUS
FB2 = Ferrite_bead_,_30_Ohm@5A: CLABCONF0: =SBEV-UCMIMX8PLUS
J1 = DC_Jack_,5.5_2.5,10A,20V: CLABCONF0: =SBEV-UCMIMX8PLUS
Q1 = Si7413DN: CLABCONF0: =SBEV-UCMIMX8PLUS
Q11-Q15 = MOSFET_N_SOT23: CLABCONF0: =SBEV-UCMIMX8PLUS; P/N: 131D10160S
R42 = RESISTOR: CLABCONF0: =SBEV-UCMIMX8PLUS; P/N: 161C30131S; Part Name: Res., 301K, 1%, 0402, 1/16W
R79 R150 R151 R154 R156 R157 R161 R165 R174 R175 = RESISTOR: CLABCONF0: =SBEV-UCMIMX8PLUS; P/N: 161D10R05S; Part Name: Res., 10R, 5%, 0603
R231 = 1.5K_1%,_0402: CLABCONF0: =SBEV-UCMIMX8PLUS
R266 = RESISTOR: CLABCONF0: =SBEV-UCMIMX8PLUS; P/N: 161C56231S; Part Name: Res., 562K, 1%, 0402, 1/16W
R268 = RESISTOR: CLABCONF0: =SBEV-UCMIMX8PLUS; P/N: 161C30021S; Part Name: Res., 30K, 1%, 0402, 1/16W
R289 = 1.5K_1%,_0402_1: CLABCONF0: =SBEV-UCMIMX8PLUS
SW1 = SW_KEY-SPST: CLABCONF0: =SBEV-UCMIMX8PLUS; P/N: 170F10010

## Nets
1V8_L: C240.2 C247.2 C260.1 C265.2 L23.1 U37.C6(CPVDD) U37.D6(AVDD) U37.G2(DCVDD) U37.G4(PLLVDD)
5V0_L: C233.2 C253.1 C256.2 L24.1 L29.1 U37.A2(SPKVDD1) U37.C2(SPKVDD2)
5V0_USB: C185.2 C237.1 J2.1(VBUS) R215.1 ; also on sheet 8
GND: BH1.2N(-) C22.2 C54.2 C59.2 C62.2 C63.2 C64.2 C68.2 C71.2 C72.2 C73.2 C74.2 C75.2 C79.2 C152.1 C158.1 C162.2 C163.2 C164.1 C165.1 C166.1 C167.1 C173.2 C175.1 C177.2 C178.2 C179.1 C181.1 C183.2 C184.2 C185.1 C186.2 C187.2 C188.1 C190.1 C192.1 C193.2 C196.2 C198.2 C199.2 C203.1 C207.2 C231.1 C233.1 C234.1 C235.1 C236.2 C237.2 C239.2 C240.1 C241.2 C246.1 C247.1 C250.2 C251.1 C252.1 C253.2 C256.1 C258.2 C259.1 C260.2 C262.2 C263.1 C264.1 C265.1 C266.1 C279.2 C371.1 C373.2 C378.2 C379.2 D9.ANODE DS2.CATHODE DS3.CATHODE E1.2 J1.2(R) J1.SH1 J1.SH2 J1.SH3 J1.SH4 J2.4(GND) J2.7(GND) J2.SH1 J2.SH2 J5.1(COM) J6.1(COM) L17.5(GND) L17.6(GND) L18.5(GND) L18.6(GND) L19.5(GND) L19.6(GND) P7.5(GND) P7.9(M9) P7.10(M10) P7.11(M11) P7.12(M12) P8.4(GND) P8.9(GND) P8.15(GND) P8.18(GND) P8.21(GND) P8.26(GND) P8.27(GND) P8.29(GND) P8.34(GND) P8.35(GND) P8.37(GND) P8.40(GND) P8.43(GND) P8.50(GND) P10.8 P11.4 P11.6 P15.8 P16.8 P17.8 P18.10 P19.8 P20.8 Q3.1(S1) Q3.4(S2) Q4.1(S) Q11.2(SOURCE) Q12.2(SOURCE) Q13.2(SOURCE) Q14.2(SOURCE) Q15.2(SOURCE) R2.1 R42.2 R45.2 R51.1 R149.1 R184.2 R187.2 R190.2 R196.2 R197.2 R199.2 R204.2 R206.2 R209.1 R212.2 R213.2 R214.2 R222.2 R237.2 R239.2 R241.2 R243.2 R245.2 R249.2 R325.1 RN17.2(RB1) RN17.3(RC1) RN17.4(RD1) SP5.1(NC) SP6.1(NC) SW1.1 U29.4(GND) U29.9(PAD) U30.4(GND) U30.9(PAD) U31.4(GND) U32.4(GND) U32.9(PAD) U35.9(VSS) U35.25(CPAD) U36.4(GND) U37.B1(SPKGND1) U37.C1(SPKGND2) U37.C7(CPGND) U37.D7(AGND) U37.F2(CIFMODE) U37.F3(DGND) U37.G5(PLLGND) U40.4(GND) U40.9(PAD) U43.3(GND) U47.2(GND) U59.2(GND) X3.2 X3.4 ; also on sheet 1 2 3 4 6 7 8
V1V8_BOOT: C197.1 U40.2(BOOT)
V1V8_COMP: C184.1 C206.1 U40.6(COMP)
V1V8_COMP_C: C206.2 R206.1
V1V8_EN: R219.2 R221.1 U40.3(EN)
V1V8_FB: R222.1 R223.2 U40.5(FB)
V1V8_RLIM: R204.1 U40.7(RLIM)
V1V8_SW: C197.2 L32.1 U40.1(SW)
V3V3_BOOT: C174.1 U30.2(BOOT)
V3V3_COMP: C180.1 C183.1 U30.6(COMP)
V3V3_COMP_C: C180.2 R199.1
V3V3_EN: R200.2 R202.1 U30.3(EN)
V3V3_FB: R197.1 R198.2 U30.5(FB)
V3V3_RLIM: R196.1 U30.7(RLIM)
V3V3_SW: C174.2 L21.1 U30.1(SW)
V5_BOOT: C189.1 U32.2(BOOT)
V5_COMP: C191.1 C196.1 U32.6(COMP)
V5_COMP_C: C191.2 R214.1
V5_FB: R208.2 R212.1 U32.5(FB)
V5_RLIM: R213.1 U32.7(RLIM)
V5_SW: C189.2 L22.1 U32.1(SW)
V5V0_EN: R203.2 R205.1 U32.3(EN)
VCC_1V8: C181.2 C203.2 C279.1 L23.2 L32.2 R156.1 R157.1 R223.1 R332.2 U47.3(VCCA) ; also on sheet 1 2 3 6
VCC_3V3: C59.1 C62.1 C63.1 C64.1 C68.1 C71.1 C72.1 C74.1 C75.1 C79.1 C152.2 C158.2 C175.2 C179.2 C192.2 C193.1 C236.1 C250.1 C251.2 C258.1 C259.2 C373.1 D14.ANODE L21.2 L29.2 P8.2(+3.3V_AUX) P8.39(3.3V_AUX) P8.41(3.3V_AUX) P8.52(+3.3V_AUX) P10.1 P11.2 P15.1 P16.1 P18.1 P19.1 P20.1 R1.2 R38.1 R44.1 R151.1 R154.1 R159.2 R166.2 R167.2 R171.2 R198.1 R235.1 R240.1 R244.1 R261.1 R362.1 R363.1 U31.8(VCC) U35.21(VDD) U36.9(VCC) U37.A3(MICVDD) U37.G3(DBVDD) U47.7(VCCB) U59.5(VIO) ; also on sheet 1 2 3 4 6 7 8
VCC_5V0: C188.2 C190.2 C371.2 L22.2 L24.2 P17.1 R161.1 R165.1 R208.1 U59.3(VCC) ; also on sheet 3 4 8
VCC_RTC: E5.1 ; also on sheet 6
AUD_SCL: R250.1 R253.1 U37.F1(SCLK)
AUD_SDA: R247.1 R252.1 U37.E2(SDA)
C_VOTN: C262.1 U37.A7(CPVOUTN)
C_VOTP: C239.1 U37.A6(CPVOUTP)
CAN2_RX/SAI2_MCLK: U59.4(RXD) ; also on sheet 6
CAN2_TX/SAI2_TXD0: U59.1(TXD) ; also on sheet 6
CAN_H: P17.2 R6.2 U59.7(CANH)
CAN_L: E6.1 P17.6 U59.6(CANL)
CAN_STBY: R325.2 U59.8(STBY)
CLKOUT2: TP2.1 U37.E4(CLKOUT2/GPIO2)
CLKOUT5: TP4.1 U37.G6(CLKOUT5)
CODEC_INT: R244.2 R248.2 U37.E3(~{CS}/GPIO6)
CODEC_PROV_I2C_SCL: R253.2 U47.1(B2)
CODEC_PROV_I2C_SDA: R252.2 U47.8(B1)
CPCA: C254.1 U37.B6(CPCA)
CPCB: C254.2 U37.B7(CPCB)
CSI1_CTRL: U35.10(I/O1.0) ; also on sheet 3
CSI1_FLASH_OUT: U35.12(I/O1.2) ; also on sheet 3
CSI1_PWR_DWN: U35.7(I/O0.6) ; also on sheet 3
CSI1_RST: U35.8(I/O0.7) ; also on sheet 3
CSI1_TRG: U35.11(I/O1.1) ; also on sheet 3
CSI2_CTRL: U35.15(I/O1.5) ; also on sheet 3
CSI2_FLASH_OUT: U35.17(I/O1.7) ; also on sheet 3
CSI2_PWR_DWN: U35.13(I/O1.3) ; also on sheet 3
CSI2_RST: U35.14(I/O1.4) ; also on sheet 3
CSI2_TRG: U35.16(I/O1.6) ; also on sheet 3
DC_FLT: C277.1 FB1.2 FB2.2 Q1.1(S) Q1.2(S) Q1.3(S) R259.2 R289.2
DC_JACK: C22.1 D9.CATHODE FB1.1 FB2.1 J1.1(CENTRAL)
DISCH_ON_H: Q11.1(GATE) Q12.1(GATE) Q13.1(GATE) Q14.1(GATE) Q15.1(GATE) R42.1 R266.2
DISCH_ONH: R266.1 R268.2 SW1.2
DSI_DISP_RESET: U35.3(I/O0.2) ; also on sheet 4
ECSPI2_MISO: P15.2 ; also on sheet 6
ECSPI2_MOSI: P15.3 ; also on sheet 6
ECSPI2_SCLK: P15.5 ; also on sheet 6
ECSPI2_SS0: P15.4 ; also on sheet 6
EEPROM_WP: R149.2 U31.7(WP)
EXPANDER_A0: R166.1 RN17.5(RD2) U35.18(A0)
EXPANDER_A1: R167.1 RN17.6(RC2) U35.23(A1)
EXPANDER_A2: R159.1 RN17.7(RB2) U35.24(A2)
GPIO1_00: P18.4 ; also on sheet 6
GPIO1_01/PWM1_OUT: P18.2 ; also on sheet 6
HOST2_USB_DN: J2.2(DN) L17.4
HOST2_USB_DP: J2.3(DP) L17.3
HP_FB: R249.1 U37.B4(HPOUTFB)
HP_J_D: J6.CN R236.1 R237.1
HP_JD: R236.2 R261.2 U37.G1(GPIO5)
HP_MICH: TP3.1 U37.F4(CLKOUT3/GPIO3)
HPOUT_L: C232.1 L31.2 R245.1 U37.B5(HPOUTL)
HPOUT_R: C255.1 L26.2 R243.1 U37.A5(HPOUTR)
I2C3_SCL: R250.2 U31.6(SCL) U35.19(SCL) ; also on sheet 4 6
I2C3_SDA: R247.2 U31.5(SDA) U35.20(SDA) ; also on sheet 4 6
I2C4_SCL/GPIO5_IO20/PWM2_OUT: P18.3 ; also on sheet 6
I2C5_SCL_3V3: P16.5 ; also on sheet 3
I2C5_SDA_3V3: P16.3 ; also on sheet 3
INT_EXP: R235.2 U35.22(\\~{IN}T)
J_MOD_8: P11.8 R155.2
JTAG_HDR_10: P11.10 R51.2
JTAG_MOD: R155.1 ; also on sheet 6
JTAG_RST: D10.CATHODE P11.9 R330.2
JTAG_RST_PU: D14.CATHODE R330.1
JTAG_TCK: P11.3 ; also on sheet 6
JTAG_TDI: P11.7 R363.2 ; also on sheet 6
JTAG_TDO: P11.5 ; also on sheet 6
JTAG_TMS: P11.1 R362.2 ; also on sheet 6
LLINEIN: C252.2 C261.1 U37.E6(IN4L)
LVDS_DISP_RESET: U35.4(I/O0.3) ; also on sheet 4
MICBIAS: C241.1 U37.A4(MICBIAS)
MODEM_AUX: C73.1 P8.24(+3.3V_AUX)
MODEM_RF_KILL#: P8.20(W_DISABLE#) R38.2 U35.1(I/O0.0)
MUX_USB2_DN: L17.1 U36.7(HSD1-)
MUX_USB2_DP: L17.2 U36.1(HSD1+)
PMIC_ON_REQ: P10.6 Q3.5(G2) ; also on sheet 6
PMIC_ON_REQn: Q3.2(G1) Q3.3(D2) R230.2
PMIC_STBY_REQ: P10.4 Q4.2(G) ; also on sheet 6
PWR_CTRL: R200.1 R203.1 R219.1 R228.2 U43.4(Y)
PWR_CTRL_IN: Q3.6(D1) Q4.6(D) R224.2 R228.1 U43.2(A)
RLINEIN: C234.2 C257.1 U37.E7(IN4R)
SAI1_MCLK/GPIO4_IO20: U47.5(A1) ; also on sheet 6
SAI2_RXC/GPIO4_IO22: R248.1 ; also on sheet 6
SAI2_TXC/GPIO4_IO25: P18.6 ; also on sheet 6
SAI3_MCLK: R254.2 ; also on sheet 6
SAI3_RXC/GPIO4_IO29: P8.22(PERST#) R44.2 ; also on sheet 6
SAI3_RXD/UART2_RTS: U37.D2(ADCDAT) ; also on sheet 6
SAI3_TXC: U37.E1(BCLK) ; also on sheet 6
SAI3_TXD: U37.D1(DACDAT) ; also on sheet 6
SAI3_TXFS: U37.D3(LRCLK) ; also on sheet 6
SD1_RESET_B/GPIO2_IO10: U47.4(A2) ; also on sheet 6
SIM_CLK: P7.3(CLK) P8.12(UIM_CLK)
SIM_IO: P7.7(IO) P8.10(UIM_DATA)
SIM_RST: P7.2(RST) P8.14(UIM_RESET)
SIM_VCC: C231.2 P7.1(VCC) P8.8(UIM_PWR)
SIM_VPP: P7.6(VPP) P8.16(UIM_VPP/GPIO42)
SPDIF_AUDIO_OUT: C54.1 P10.2 R45.1 R48.2
SPDIF_TX: C53.2 ; also on sheet 6
SYS_RST_PMIC: D10.ANODE P10.3 ; also on sheet 6
TOUCH_RESET: U35.5(I/O0.4) ; also on sheet 4
UART1_CTS/UART3_RXD: P20.6 ; also on sheet 6
UART1_RTS/UART3_TXD: P20.3 ; also on sheet 6
UART1_RXD: P20.2 ; also on sheet 6
UART1_TXD: P20.4 ; also on sheet 6
UART4_RXD: P19.2 ; also on sheet 6
UART4_TXD: P19.4 ; also on sheet 6
USB2_DN: U36.5(D-) ; also on sheet 6
USB2_DP: U36.3(D+) ; also on sheet 6
USB2_MINIPCI_DN: P8.36(USB_D-) U36.6(HSD2-)
USB2_MINIPCI_DP: P8.38(USB_D+) U36.2(HSD2+)
USB2_RX_N: L19.2 ; also on sheet 6
USB2_RX_P: L19.1 ; also on sheet 6
USB2_SEL: E1.1 R171.1 U36.10(SEL)
USB2_SSRXN: J2.5(SSRXN) L19.3
USB2_SSRXP: J2.6(SSRXP) L19.4
USB2_SSTXN: J2.8(SSTXN) L18.3
USB2_SSTXP: J2.9(SSTXP) L18.4
USB2_TX_N: L18.2 ; also on sheet 6
USB2_TX_P: L18.1 ; also on sheet 6
USB2_VBUS: R215.2 ; also on sheet 6
USB_PWR_EN: U35.2(I/O0.1) ; also on sheet 8
V_COIN: BH1.1P(+) BH1.3P(+) R231.1
V_SOM: C166.2 C167.2 C207.1 E2.1 R79.1 R150.1 R182.1 R183.2 R202.2 R205.2 R221.2 R224.1 R230.1 U43.5(VCC) ; also on sheet 6
V_SOM_L: C164.2 C165.2 E2.2 L20.2 R181.1 R183.1
VCOIN: E5.2 R231.2
VDC_IN: C162.1 C163.1 C177.1 C178.1 C186.1 C187.1 C198.1 C199.1 C378.1 C379.1 Q1.5(D) Q1.6(D) Q1.7(D) Q1.8(D) Q1.9(D-pad) R174.1 R175.1 R180.2 U29.8(VIN) U30.8(VIN) U32.8(VIN) U40.8(VIN)
VGS_Q5: C277.2 Q1.4(G) R259.1 R268.1
VMIDC: C266.2 U37.C5(VMIDC)
VSOM_BOOT: C161.1 U29.2(BOOT)
VSOM_COMP: C172.1 C173.1 U29.6(COMP)
VSOM_COMP_C: C172.2 R190.1
VSOM_EN: R180.1 U29.3(EN)
VSOM_FB: R181.2 R187.1 U29.5(FB)
VSOM_LED: DS3.ANODE R182.2
VSOM_RLIM: R184.1 U29.7(RLIM)
VSOM_SW: C161.2 L20.1 U29.1(SW)
XTALI_24M: C246.2 R254.1 R255.1 U37.G7(MCLK/XTI) X3.1
XTALO_24M: C263.2 R255.2 U37.F7(XTO) X3.3
N19892073: C261.2 J5.4(L)
N19892076: C257.2 J5.3(R)
N19892121: C264.2 J6.3(R) L26.1
N19892127: C235.2 J6.4(L) L31.1
N19892416: J6.CO R240.2
N19892449: C232.2 R239.1
N19892528: C255.2 R241.1
N19925292: C53.1 R48.1
N19926151: R1.1 R2.2 U31.3(A2)
N19955313: Q11.3(DRAIN) R79.2 R150.2
N19955468: Q12.3(DRAIN) R151.2 R154.2
N19955474: Q13.3(DRAIN) R156.2 R157.2
N19955480: Q14.3(DRAIN) R161.2 R165.2
N19955519: DS2.ANODE R289.1
N19955684: Q15.3(DRAIN) R174.2 R175.2
N19989322: R209.2 U36.8(\\~{O}E)
N20022806: R332.1 U47.6(OE)
N20023604: E6.2 R6.1

Not connected (* = marked no-connect by the designer): J5 2(AUX)* CN* CO*; J6 2(AUX)*; P7 4(RSVD4)* 8(RSVD8)*; P8 1(WAKE#/MIC1P)* 3(COEX1/MIC1N)* 5(COEX2/EAR1P)* 6(+1.5V/NC)* 7(CLKREQ#/EAR1N)* 11(REFCLK-/UART_CTS)* 13(REFCLK+/UART_RTS)* 17(RSVD/UART_RXD)* 19(RSVD/UART_TXD)* 23(PER_N0/NC)* 25(PER_P0/NC)* 28(+1.5V/NC)* 30(GPIO9/SMB_CLK)* 31(PET_N0/NC)* 32(GPIO6/SMB_DATA)* 33(PET_P0/NC)* 42(LED_WWAN#)* 44(LED_WLAN#/UART_RI)* 45(RSVD/PCM_CLK)* 46(LED_WPAN#/UART_DTR)* 47(RSVD/PCM_OUT)* 48(+1.5V/NC)* 49(RSVD/PCM_IN)* 51(RSVD/PCM_SYNC)*; P10 5* 7*; P15 6* 7*; P16 2* 4* 6* 7*; P17 3* 4* 5* 7*; P18 5* 7* 8* 9*; P19 3* 5* 6* 7*; P20 5* 7*; RN17 1(RA1)* 8(RA2)*; U31 1(NC)* 2(NC)*; U35 6(I/O0.5)*; U37 A1(SPKOUTLP)* B2(SPKOUTRP)* B3(SPKOUTLN)* C3(SPKOUTRN)* C4(IN1L)* D4(IN1R)* D5(IN2L)* E5(IN2R)* F5(IN3L)* F6(IN3R)*

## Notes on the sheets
sheet 9
- DCVDD
  DBVDD
  MICVDD
  AVDD
  PLLVDD
  CPVDD
  SPKVDD
- 1.62V - 2.0V
  1.62V - 3.6V
  1.70V - 3.6V
  1.70V - 2.0V
  1.70V - 2.0V
  1.70V - 2.0V
  1.70V - 5.5V
- PLUGGED: High
  Removed: Low
- Zobel Networks: close to
  WM8962B
- Plugged: CO
  connected to CN
- DNP
- Clk/Osc enable; p#163; T104/105
- DNP
- DNP
- PLUGGED: High
  Removed: Low
- DNP
- DNP
- I2C over GPIO
  provision
- XTAL provision
  Not populated
sheet 10
- USB #2 connector
- USB #2 mux (USB2 signals only)
- 90 ohm
- # 90-Ohm differential pairs
- # 90-Ohm differential pairs
- E1 operation
  Open:         for miniPCIe socket P3
  Shorted:      for USB conn. J2
- mini-PCIe socket
- Place close to P3
- int. PU
sheet 11
- DC input
- Vin 8V-18V
- Discharge
- P-MOSFET, 8.3A, 20V
- -Vgs:2-4.5V
- 3A, 20V
- Vgs:2.7-6.0V
- RTC battery
- DNP
sheet 12
- VCC_3V3
- VCC_5V
- Vout=0.8*(1+56.2/17.8)=3.33V
- Vout=5V
  Iout max = 3A
- Vout=3.3V
  Iout max = 3A
- Vout=0.8*(1+64.9/12.4)=4.987V
- RLIM = 100k => ~4A
- RLIM = 100k => ~4A
- DNP
- DNP
- PWR_CTRLn
- V_SOM (3A)
- Vout=3.7V
  Iout max = 3A
- Current measure
- DNP
- DNP
- Vout=0.8*(1+64.9/17.8)=3.72V
- RLIM = 100k => ~4A
- VCC_1V8
- Vout=0.8*(1+22.1/17.8)=1.79V
- Vout=1.8V
  Iout max = 3A
- RLIM = 100k => ~4A
- DNP
sheet 13
- CAN bus
- UARTs
- System /Miscellaneous
- EEPROM
- 3.3V x 2mA = 6.6mW
- I2C slave address: 0x54..0x57
- GPIO expander
- GPIO
- SPI
- I2C Address:
  0x20
- JTAG
- I2C
- NXP refdes layout
- TMS
- VCC
- TCK
- GND
- TDI
- TDO
- GND
